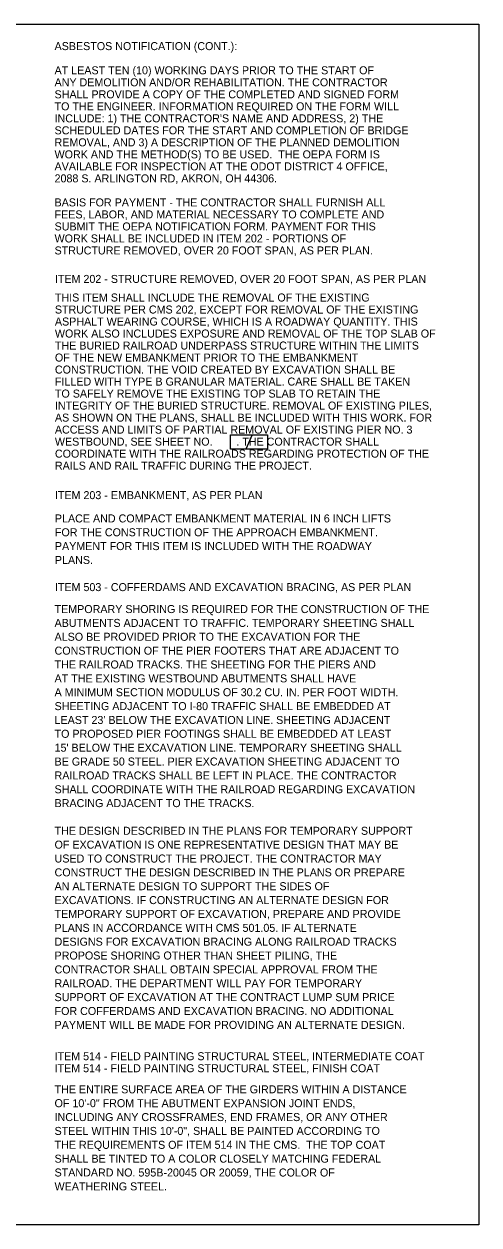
# Model space of a CAD drawing. Extents: x 1530552 to 1530730, y 675304 to 675366.
# Drawn here: x 1530722.01 to 1530729.97, y 675331.91 to 675352.91 of the extents above; entities that cross this region are included whole.
import ezdxf

# ---------------------------------------------------------------- set-up
doc = ezdxf.new("R2010")
doc.units = 0
for name, color, linetype in [('BR_P_Gen_Text', 7, 'Continuous'), ('Default', 7, 'Continuous'), ('SC_Scratch1', 7, 'Continuous')]:
    doc.layers.add(name, color=color, linetype=linetype)

msp = doc.modelspace()

# ---------------------------------------------------------------- linework, layer by layer
at = {"layer": 'BR_P_Gen_Text'}
msp.add_line((1530726.004, 675345.729), (1530725.889, 675345.479), dxfattribs=at)
for points in [[(1530699.468, 675352.914), (1530729.968, 675352.914), (1530729.968, 675331.914), (1530699.468, 675331.914)], [(1530725.622, 675345.729), (1530726.272, 675345.729), (1530726.272, 675345.479), (1530725.622, 675345.479)]]:
    msp.add_lwpolyline(points, close=True, dxfattribs=at)

# ---------------------------------------------------------------- texts
for s, p in [('ITEM 202 - STRUCTURE REMOVED, OVER 20 FOOT SPAN, AS PER PLAN', (1530722.553, 675348.387)), ('THIS ITEM SHALL INCLUDE THE REMOVAL OF THE EXISTING', (1530722.553, 675348.062)), ('STRUCTURE PER CMS 202, EXCEPT FOR REMOVAL OF THE EXISTING ', (1530722.553, 675347.852)), ('ASPHALT WEARING COURSE, WHICH IS A ROADWAY QUANTITY. THIS ', (1530722.553, 675347.642)), ('WORK ALSO INCLUDES EXPOSURE AND REMOVAL OF THE TOP SLAB OF ', (1530722.553, 675347.432)), ('THE BURIED RAILROAD UNDERPASS STRUCTURE WITHIN THE LIMITS ', (1530722.553, 675347.222)), ('OF THE NEW EMBANKMENT PRIOR TO THE EMBANKMENT ', (1530722.553, 675347.012)), ('CONSTRUCTION. THE VOID CREATED BY EXCAVATION SHALL BE ', (1530722.553, 675346.802)), ('FILLED WITH TYPE B GRANULAR MATERIAL. CARE SHALL BE TAKEN ', (1530722.553, 675346.592)), ('TO SAFELY REMOVE THE EXISTING TOP SLAB TO RETAIN THE ', (1530722.553, 675346.382)), ('INTEGRITY OF THE BURIED STRUCTURE. REMOVAL OF EXISTING PILES,', (1530722.553, 675346.172)), ('AS SHOWN ON THE PLANS, SHALL BE INCLUDED WITH THIS WORK. FOR ', (1530722.553, 675345.962)), ('ACCESS AND LIMITS OF PARTIAL REMOVAL OF EXISTING PIER NO. 3 ', (1530722.553, 675345.752)), ('WESTBOUND, SEE SHEET NO.        . THE CONTRACTOR SHALL', (1530722.553, 675345.542)), ('COORDINATE WITH THE RAILROADS REGARDING PROTECTION OF THE ', (1530722.553, 675345.332)), ('RAILS AND RAIL TRAFFIC DURING THE PROJECT.', (1530722.553, 675345.122)), ('ITEM 203 - EMBANKMENT, AS PER PLAN', (1530722.553, 675344.606)), ('PLACE AND COMPACT EMBANKMENT MATERIAL IN 6 INCH LIFTS', (1530722.553, 675344.199)), ('FOR THE CONSTRUCTION OF THE APPROACH EMBANKMENT.', (1530722.553, 675343.957)), ('PAYMENT FOR THIS ITEM IS INCLUDED WITH THE ROADWAY', (1530722.553, 675343.715)), ('PLANS.', (1530722.553, 675343.472)), ('ITEM 503 - COFFERDAMS AND EXCAVATION BRACING, AS PER PLAN', (1530722.553, 675342.998)), ('TEMPORARY SHORING IS REQUIRED FOR THE CONSTRUCTION OF THE', (1530722.547, 675342.614)), ('ABUTMENTS ADJACENT TO TRAFFIC. TEMPORARY SHEETING SHALL', (1530722.547, 675342.372)), ('ALSO BE PROVIDED PRIOR TO THE EXCAVATION FOR THE', (1530722.547, 675342.13)), ('CONSTRUCTION OF THE PIER FOOTERS THAT ARE ADJACENT TO', (1530722.547, 675341.887)), ('THE RAILROAD TRACKS. THE SHEETING FOR THE PIERS AND ', (1530722.547, 675341.645)), ('AT THE EXISTING WESTBOUND ABUTMENTS SHALL HAVE', (1530722.547, 675341.402)), ('A MINIMUM SECTION MODULUS OF 30.2 CU. IN. PER FOOT WIDTH.', (1530722.547, 675341.16)), ('SHEETING ADJACENT TO I-80 TRAFFIC SHALL BE EMBEDDED AT', (1530722.547, 675340.917)), ("LEAST 23' BELOW THE EXCAVATION LINE. SHEETING ADJACENT", (1530722.547, 675340.675)), ('TO PROPOSED PIER FOOTINGS SHALL BE EMBEDDED AT LEAST', (1530722.547, 675340.433)), ("15' BELOW THE EXCAVATION LINE. TEMPORARY SHEETING SHALL", (1530722.547, 675340.19)), ('BE GRADE 50 STEEL. PIER EXCAVATION SHEETING ADJACENT TO ', (1530722.547, 675339.948)), ('RAILROAD TRACKS SHALL BE LEFT IN PLACE. THE CONTRACTOR', (1530722.547, 675339.705)), ('SHALL COORDINATE WITH THE RAILROAD REGARDING EXCAVATION', (1530722.547, 675339.463)), ('BRACING ADJACENT TO THE TRACKS. ', (1530722.547, 675339.221)), ('THE DESIGN DESCRIBED IN THE PLANS FOR TEMPORARY SUPPORT ', (1530722.547, 675338.737)), ('OF EXCAVATION IS ONE REPRESENTATIVE DESIGN THAT MAY BE ', (1530722.547, 675338.495)), ('USED TO CONSTRUCT THE PROJECT. THE CONTRACTOR MAY ', (1530722.547, 675338.252)), ('CONSTRUCT THE DESIGN DESCRIBED IN THE PLANS OR PREPARE ', (1530722.547, 675338.01)), ('AN ALTERNATE DESIGN TO SUPPORT THE SIDES OF ', (1530722.547, 675337.768)), ('EXCAVATIONS. IF CONSTRUCTING AN ALTERNATE DESIGN FOR ', (1530722.547, 675337.525)), ('TEMPORARY SUPPORT OF EXCAVATION, PREPARE AND PROVIDE ', (1530722.547, 675337.283)), ('PLANS IN ACCORDANCE WITH CMS 501.05. IF ALTERNATE ', (1530722.547, 675337.04)), ('DESIGNS FOR EXCAVATION BRACING ALONG RAILROAD TRACKS ', (1530722.547, 675336.798)), ('PROPOSE SHORING OTHER THAN SHEET PILING, THE ', (1530722.547, 675336.556)), ('CONTRACTOR SHALL OBTAIN SPECIAL APPROVAL FROM THE ', (1530722.547, 675336.313)), ('RAILROAD. THE DEPARTMENT WILL PAY FOR TEMPORARY ', (1530722.547, 675336.071)), ('SUPPORT OF EXCAVATION AT THE CONTRACT LUMP SUM PRICE ', (1530722.547, 675335.828)), ('FOR COFFERDAMS AND EXCAVATION BRACING. NO ADDITIONAL ', (1530722.547, 675335.586)), ('PAYMENT WILL BE MADE FOR PROVIDING AN ALTERNATE DESIGN.', (1530722.547, 675335.343)), ('ITEM 514 - FIELD PAINTING STRUCTURAL STEEL, INTERMEDIATE COAT', (1530722.547, 675334.795)), ('ITEM 514 - FIELD PAINTING STRUCTURAL STEEL, FINISH COAT', (1530722.547, 675334.585)), ('THE ENTIRE SURFACE AREA OF THE GIRDERS WITHIN A DISTANCE ', (1530722.547, 675334.216)), ('OF 10\'-0" FROM THE ABUTMENT EXPANSION JOINT ENDS, ', (1530722.547, 675333.974)), ('INCLUDING ANY CROSSFRAMES, END FRAMES, OR ANY OTHER ', (1530722.547, 675333.731)), ('STEEL WITHIN THIS 10\'-0", SHALL BE PAINTED ACCORDING TO ', (1530722.547, 675333.489)), ('THE REQUIREMENTS OF ITEM 514 IN THE CMS.  THE TOP COAT ', (1530722.547, 675333.246)), ('SHALL BE TINTED TO A COLOR CLOSELY MATCHING FEDERAL ', (1530722.547, 675333.004)), ('STANDARD NO. 595B-20045 OR 20059, THE COLOR OF ', (1530722.547, 675332.762)), ('WEATHERING STEEL.', (1530722.547, 675332.519))]:
    msp.add_text(s, height=0.14, dxfattribs=at).set_placement(p)
at = {"layer": 'Default'}
for s, p in [('ASBESTOS NOTIFICATION (CONT.):', (1530722.547, 675352.458)), ('AT LEAST TEN (10) WORKING DAYS PRIOR TO THE START OF ', (1530722.547, 675352.035)), ('ANY DEMOLITION AND/OR REHABILITATION. THE CONTRACTOR ', (1530722.547, 675351.825)), ('SHALL PROVIDE A COPY OF THE COMPLETED AND SIGNED FORM ', (1530722.547, 675351.615)), ('TO THE ENGINEER. INFORMATION REQUIRED ON THE FORM WILL ', (1530722.547, 675351.405)), ("INCLUDE: 1) THE CONTRACTOR'S NAME AND ADDRESS, 2) THE ", (1530722.547, 675351.195)), ('SCHEDULED DATES FOR THE START AND COMPLETION OF BRIDGE ', (1530722.547, 675350.985)), ('REMOVAL, AND 3) A DESCRIPTION OF THE PLANNED DEMOLITION ', (1530722.547, 675350.775)), ('WORK AND THE METHOD(S) TO BE USED.  THE OEPA FORM IS ', (1530722.547, 675350.565)), ('AVAILABLE FOR INSPECTION AT THE ODOT DISTRICT 4 OFFICE, ', (1530722.547, 675350.355)), ('2088 S. ARLINGTON RD, AKRON, OH 44306.', (1530722.547, 675350.145)), ('BASIS FOR PAYMENT - THE CONTRACTOR SHALL FURNISH ALL ', (1530722.547, 675349.725)), ('FEES, LABOR, AND MATERIAL NECESSARY TO COMPLETE AND ', (1530722.547, 675349.515)), ('SUBMIT THE OEPA NOTIFICATION FORM. PAYMENT FOR THIS ', (1530722.547, 675349.305)), ('WORK SHALL BE INCLUDED IN ITEM 202 - PORTIONS OF ', (1530722.547, 675349.095)), ('STRUCTURE REMOVED, OVER 20 FOOT SPAN, AS PER PLAN.', (1530722.547, 675348.885))]:
    msp.add_text(s, height=0.14, dxfattribs=at).set_placement(p)
at = {"layer": 'SC_Scratch1'}
for p in [(1530725.779, 675345.598), (1530726.103, 675345.598)]:
    msp.add_text('X', height=0.0131, dxfattribs=at).set_placement(p)

doc.saveas('drawing.dxf')
